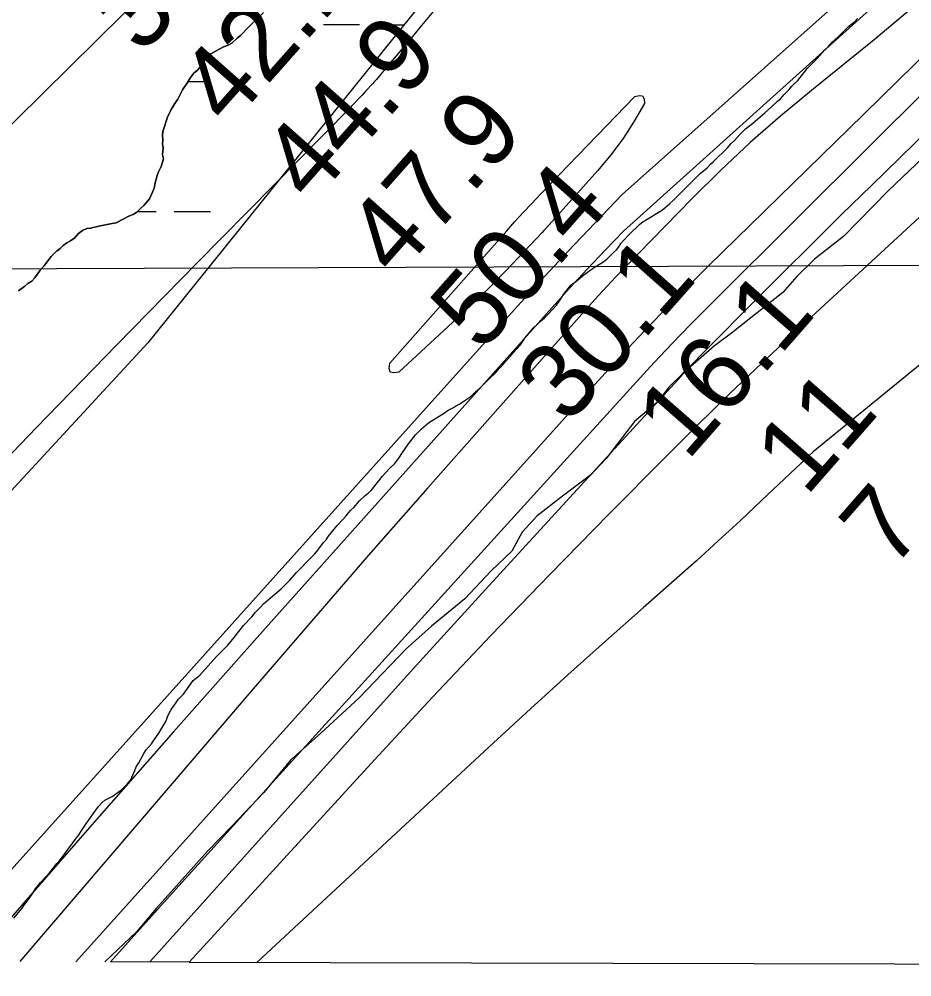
# Model space of a CAD drawing. Extents: x 3172297 to 3210190, y 958463 to 983887.
# Drawn here: x 3192652 to 3193444, y 963866 to 964716 of the extents above; entities that cross this region are included whole.
import ezdxf

# ---------------------------------------------------------------- set-up
doc = ezdxf.new("R2010")
doc.units = 0
for name, color, linetype in [('V-RIVR-EDGE', 7, 'Continuous'), ('V-RIVR-RANG', 7, 'Continuous'), ('V-SITE-VEGE', 7, 'Continuous'), ('V-TOPO-BNDY', 7, 'Continuous'), ('V-TOPO-DPTH', 7, 'Continuous'), ('V-TOPO-MAJR', 7, 'Continuous'), ('V-TOPO-MINR', 7, 'Continuous'), ('V-TOPO-SHOR', 7, 'Continuous'), ('V-TOPO-WATR', 7, 'Continuous'), ('V-WETL-SWMP', 7, 'Continuous')]:
    doc.layers.add(name, color=color, linetype=linetype)

msp = doc.modelspace()

# ---------------------------------------------------------------- linework, layer by layer
at = {"layer": 'V-RIVR-EDGE'}
msp.add_lwpolyline([(3193460.57, 964599.24), (3193422.95, 964563.51), (3193383.62, 964523.24), (3193357.7, 964502.84), (3193342.02, 964487.52), (3193329.48, 964473.34), (3193283.9, 964437.34), (3193268.81, 964426.01), (3193240.88, 964401.34), (3193228.34, 964389.15), (3193218.36, 964376.1), (3193197.85, 964358.81), (3193172.75, 964325.89), (3193159.07, 964311.14), (3193134, 964292.72), (3193111.5, 964274.87), (3193098.38, 964260.68), (3193089.25, 964243.79), (3193071.29, 964226.78), (3193047.63, 964201.53), (3193018, 964177.15), (3192995.5, 964157.02), (3192953.88, 964113.63), (3192919.69, 964082.44), (3192892.9, 964058.34), (3192869.23, 964029.69), (3192841.02, 963999.9), (3192819.64, 963978.07), (3192774.02, 963927), (3192756.35, 963906.01), (3192728.14, 963879.45)], dxfattribs=at)
at = {"layer": 'V-SITE-VEGE'}
for p, q in [((3192868.96, 964721.74), (3192861.75, 964714.48)), ((3192859.01, 964712.06), (3192856.26, 964709.3)), ((3192861.75, 964714.48), (3192859.01, 964712.06)), ((3193387.66, 964709.31), (3193393.26, 964713.64)), ((3193393.26, 964713.64), (3193395.84, 964716.24)), ((3192856.26, 964709.3), (3192848.71, 964701.35)), ((3193378.64, 964700.01), (3193387.66, 964709.31)), ((3192840.81, 964694.44), (3192837.71, 964692.7)), ((3192845.96, 964699.28), (3192840.81, 964694.44)), ((3192848.71, 964701.35), (3192845.96, 964699.28)), ((3193369.6, 964691.13), (3193373.26, 964695.24)), ((3193373.26, 964695.24), (3193378.64, 964700.01)), ((3192822.24, 964685.08), (3192819.15, 964682.31)), ((3192830.15, 964689.58), (3192822.24, 964685.08)), ((3192833.59, 964691.31), (3192830.15, 964689.58)), ((3192837.71, 964692.7), (3192833.59, 964691.31)), ((3193360.15, 964681.18), (3193366.16, 964687.89)), ((3193366.16, 964687.89), (3193369.6, 964691.13)), ((3192816.06, 964678.51), (3192812.64, 964672.99)), ((3192819.15, 964682.31), (3192816.06, 964678.51)), ((3193351.55, 964672.31), (3193360.15, 964681.18)), ((3192807.14, 964667.81), (3192804.4, 964664.01)), ((3192810.58, 964670.57), (3192807.14, 964667.81)), ((3192812.64, 964672.99), (3192810.58, 964670.57)), ((3193342.74, 964661.28), (3193351.55, 964672.31)), ((3192801.66, 964659.52), (3192797.2, 964652.96)), ((3192804.4, 964664.01), (3192801.66, 964659.52)), ((3193337.58, 964656.3), (3193342.74, 964661.28)), ((3192797.2, 964652.96), (3192793.09, 964644.68)), ((3193330.49, 964648.52), (3193335.21, 964653.49)), ((3193335.21, 964653.49), (3193337.58, 964656.3)), ((3192793.09, 964644.68), (3192790.35, 964640.88)), ((3193319.52, 964637.91), (3193324.9, 964643.1)), ((3193324.9, 964643.1), (3193327.48, 964645.05)), ((3193327.48, 964645.05), (3193330.49, 964648.52)), ((3192787.61, 964636.4), (3192784.19, 964629.84)), ((3192790.35, 964640.88), (3192787.61, 964636.4)), ((3193313.71, 964632.71), (3193319.52, 964637.91)), ((3192784.19, 964629.84), (3192779.75, 964616.05)), ((3193302.96, 964623.4), (3193307.26, 964627.3)), ((3193307.26, 964627.3), (3193313.71, 964632.71)), ((3193291.35, 964613.45), (3193296.29, 964618.42)), ((3193296.29, 964618.42), (3193302.96, 964623.4)), ((3192779.75, 964616.05), (3192779.42, 964612.95)), ((3192779.42, 964612.95), (3192779.78, 964608.82)), ((3192779.78, 964608.82), (3192779.45, 964605.03)), ((3193283.6, 964605.44), (3193286.62, 964608.25)), ((3193286.62, 964608.25), (3193291.35, 964613.45)), ((3192779.45, 964605.03), (3192780.15, 964601.58)), ((3192780.15, 964601.58), (3192779.48, 964595.38)), ((3193267.7, 964589.21), (3193280.38, 964601.76)), ((3193280.38, 964601.76), (3193283.6, 964605.44)), ((3192780.18, 964591.94), (3192778.13, 964585.05)), ((3192779.48, 964595.38), (3192780.18, 964591.94)), ((3192778.13, 964585.05), (3192775.74, 964580.21)), ((3193256.3, 964578.82), (3193262.54, 964584.02)), ((3193262.54, 964584.02), (3193265.33, 964587.05)), ((3193265.33, 964587.05), (3193267.7, 964589.21)), ((3192774.71, 964577.11), (3192773.01, 964570.56)), ((3192775.74, 964580.21), (3192774.71, 964577.11)), ((3193232.65, 964555.23), (3193253.72, 964576.44)), ((3193253.72, 964576.44), (3193256.3, 964578.82)), ((3192773.01, 964570.56), (3192772, 964565.74)), ((3192770.63, 964562.29), (3192767.89, 964556.42)), ((3192772, 964565.74), (3192770.63, 964562.29)), ((3192762.74, 964550.55), (3192760, 964547.79)), ((3192767.89, 964556.42), (3192762.74, 964550.55)), ((3193222.76, 964546.57), (3193229.43, 964552.2)), ((3193229.43, 964552.2), (3193232.65, 964555.23)), ((3192750.03, 964541.21), (3192738.34, 964534.97)), ((3192753.47, 964542.6), (3192750.03, 964541.21)), ((3192756.56, 964544.68), (3192753.47, 964542.6)), ((3192760, 964547.79), (3192756.56, 964544.68)), ((3193205.32, 964535.95), (3193222.76, 964546.57)), ((3192722.85, 964532.17), (3192715.62, 964530.42)), ((3192734.9, 964534.61), (3192722.85, 964532.17)), ((3192738.34, 964534.97), (3192734.9, 964534.61)), ((3193193.28, 964524.69), (3193202.74, 964533.78)), ((3193202.74, 964533.78), (3193205.32, 964535.95)), ((3192704.96, 964525.56), (3192701.19, 964521.07)), ((3192708.4, 964528.33), (3192704.96, 964525.56)), ((3192712.18, 964530.07), (3192708.4, 964528.33)), ((3192715.62, 964530.42), (3192712.18, 964530.07)), ((3193188.55, 964519.72), (3193193.28, 964524.69)), ((3192691.21, 964514.84), (3192688.81, 964512.42)), ((3192694.65, 964517.26), (3192691.21, 964514.84)), ((3192697.75, 964518.99), (3192694.65, 964517.26)), ((3192700.84, 964521.07), (3192697.75, 964518.99)), ((3192701.19, 964521.07), (3192700.84, 964521.07)), ((3193184.04, 964513.66), (3193185.97, 964516.69)), ((3193185.97, 964516.69), (3193188.55, 964519.72)), ((3192685.38, 964510), (3192680.57, 964505.16)), ((3192686.06, 964510.35), (3192685.38, 964510)), ((3192688.81, 964512.42), (3192686.06, 964510.35)), ((3193173.5, 964502.84), (3193179.31, 964508.9)), ((3193179.31, 964508.9), (3193181.89, 964511.07)), ((3193181.89, 964511.07), (3193184.04, 964513.66)), ((3192676.8, 964500.33), (3192674.4, 964496.88)), ((3192680.57, 964505.16), (3192676.8, 964500.33)), ((3193160.81, 964494.61), (3193170.92, 964500.89)), ((3193170.92, 964500.89), (3193173.5, 964502.84)), ((3192670.96, 964493.08), (3192666.16, 964486.17)), ((3192674.4, 964496.88), (3192670.96, 964493.08)), ((3193151.98, 964488.11), (3193160.81, 964494.61)), ((3192659.98, 964481.33), (3192657.23, 964478.91)), ((3192663.42, 964483.41), (3192659.98, 964481.33)), ((3192666.16, 964486.17), (3192663.42, 964483.41)), ((3193141.66, 964479.88), (3193147.04, 964483.99)), ((3193147.04, 964483.99), (3193151.98, 964488.11)), ((3192657.23, 964478.91), (3192651.74, 964474.76)), ((3193135, 964471.44), (3193139.08, 964476.85)), ((3193139.08, 964476.85), (3193141.66, 964479.88)), ((3193128.77, 964461.93), (3193130.71, 964464.31)), ((3193130.71, 964464.31), (3193135, 964471.44)), ((3193121.46, 964453.93), (3193128.77, 964461.93)), ((3193108.56, 964442.02), (3193115.87, 964448.73)), ((3193115.87, 964448.73), (3193118.24, 964450.68)), ((3193118.24, 964450.68), (3193121.46, 964453.93)), ((3193100.83, 964432.72), (3193108.56, 964442.02)), ((3193096.96, 964426.89), (3193100.83, 964432.72)), ((3193090.52, 964419.75), (3193096.96, 964426.89)), ((3193083.43, 964411.75), (3193088.15, 964416.72)), ((3193088.15, 964416.72), (3193090.52, 964419.75)), ((3193075.04, 964402.23), (3193078.27, 964406.12)), ((3193078.27, 964406.12), (3193080.85, 964408.72)), ((3193080.85, 964408.72), (3193083.43, 964411.75)), ((3193060.42, 964388.16), (3193070.1, 964397.68)), ((3193070.1, 964397.68), (3193072.68, 964399.85)), ((3193072.68, 964399.85), (3193075.04, 964402.23)), ((3193057.63, 964385.78), (3193060.42, 964388.16)), ((3193045.8, 964376.25), (3193050.96, 964379.93)), ((3193050.96, 964379.93), (3193053.97, 964382.32)), ((3193053.97, 964382.32), (3193057.63, 964385.78)), ((3193032.88, 964368.87), (3193037.4, 964371.26)), ((3193037.4, 964371.26), (3193039.12, 964372.56)), ((3193039.12, 964372.56), (3193043, 964374.51)), ((3193043, 964374.51), (3193045.8, 964376.25)), ((3193015.44, 964357.6), (3193029.43, 964366.49)), ((3193029.43, 964366.49), (3193032.88, 964368.87)), ((3193009.2, 964352.41), (3193015.44, 964357.6)), ((3192997.6, 964338.99), (3193003.83, 964346.99)), ((3193003.83, 964346.99), (3193009.2, 964352.41)), ((3192991.59, 964330.56), (3192997.6, 964338.99)), ((3192989.66, 964327.32), (3192991.59, 964330.56)), ((3192980.85, 964317.16), (3192985.36, 964321.7)), ((3192985.36, 964321.7), (3192989.66, 964327.32)), ((3192974.62, 964310.45), (3192980.85, 964317.16)), ((3192964.52, 964297.69), (3192974.62, 964310.45)), ((3192959.14, 964293.14), (3192961.94, 964295.31)), ((3192961.94, 964295.31), (3192964.52, 964297.69)), ((3192949.04, 964282.54), (3192954.2, 964288.38)), ((3192954.2, 964288.38), (3192959.14, 964293.14)), ((3192942.38, 964275.19), (3192944.31, 964277.78)), ((3192944.31, 964277.78), (3192946.46, 964280.16)), ((3192946.46, 964280.16), (3192949.04, 964282.54)), ((3192934.42, 964266.53), (3192939.8, 964272.59)), ((3192939.8, 964272.59), (3192942.38, 964275.19)), ((3192926.69, 964257.23), (3192934.42, 964266.53)), ((3192916.38, 964243.61), (3192922.18, 964251.39)), ((3192922.18, 964251.39), (3192924.54, 964253.99)), ((3192924.54, 964253.99), (3192926.69, 964257.23)), ((3192914.23, 964241.01), (3192916.38, 964243.61)), ((3192906.71, 964233.87), (3192914.23, 964241.01)), ((3192898.11, 964224.78), (3192902.62, 964229.33)), ((3192902.62, 964229.33), (3192906.71, 964233.87)), ((3192888.01, 964213.54), (3192892.73, 964218.51)), ((3192892.73, 964218.51), (3192898.11, 964224.78)), ((3192875.32, 964202.28), (3192884.78, 964210.5)), ((3192884.78, 964210.5), (3192888.01, 964213.54)), ((3192869.08, 964197.08), (3192875.32, 964202.28)), ((3192861.55, 964189.29), (3192866.71, 964194.49)), ((3192866.71, 964194.49), (3192869.08, 964197.08)), ((3192851.24, 964177.82), (3192858.54, 964185.62)), ((3192858.54, 964185.62), (3192861.55, 964189.29)), ((3192842.86, 964167.23), (3192851.24, 964177.82)), ((3192837.27, 964160.53), (3192842.86, 964167.23)), ((3192827.39, 964150.35), (3192837.27, 964160.53)), ((3192819.86, 964142.13), (3192827.39, 964150.35)), ((3192814.92, 964136.3), (3192819.86, 964142.13)), ((3192806.75, 964128.94), (3192812.56, 964133.91)), ((3192812.56, 964133.91), (3192814.92, 964136.3)), ((3192798.16, 964117.04), (3192806.75, 964128.94)), ((3192793.43, 964112.07), (3192798.16, 964117.04)), ((3192788.49, 964105.36), (3192791.07, 964108.61)), ((3192791.07, 964108.61), (3192793.43, 964112.07)), ((3192783.56, 964095.86), (3192784.85, 964098.88)), ((3192784.85, 964098.88), (3192786.77, 964102.77)), ((3192786.77, 964102.77), (3192788.49, 964105.36)), ((3192776.27, 964082.25), (3192782.5, 964092.62)), ((3192782.5, 964092.62), (3192783.56, 964095.86)), ((3192771.33, 964075.54), (3192776.27, 964082.25)), ((3192764.89, 964067.54), (3192769.62, 964072.95)), ((3192769.62, 964072.95), (3192771.33, 964075.54)), ((3192762.74, 964064.3), (3192764.89, 964067.54)), ((3192758.46, 964055.88), (3192760.38, 964059.98)), ((3192760.38, 964059.98), (3192762.74, 964064.3)), ((3192750.96, 964040.75), (3192754.81, 964049.18)), ((3192754.81, 964049.18), (3192756.09, 964052.42)), ((3192756.09, 964052.42), (3192758.46, 964055.88)), ((3192749.02, 964038.16), (3192750.96, 964040.75)), ((3192740.21, 964029.93), (3192743, 964032.1)), ((3192743, 964032.1), (3192746.66, 964035.56)), ((3192746.66, 964035.56), (3192749.02, 964038.16)), ((3192725.57, 964020.39), (3192728.36, 964022.99)), ((3192728.36, 964022.99), (3192734.83, 964026.25)), ((3192734.83, 964026.25), (3192740.21, 964029.93)), ((3192717.83, 964010.88), (3192722.56, 964017.15)), ((3192722.56, 964017.15), (3192725.57, 964020.39)), ((3192711.39, 964001.58), (3192717.83, 964010.88)), ((3192707.96, 963996.18), (3192711.39, 964001.58)), ((3192688.21, 963969.15), (3192705.81, 963993.15)), ((3192705.81, 963993.15), (3192707.96, 963996.18)), ((3192679.18, 963958.34), (3192685.84, 963966.56)), ((3192685.84, 963966.56), (3192688.21, 963969.15)), ((3192671.23, 963949.69), (3192675.74, 963954.45)), ((3192675.74, 963954.45), (3192679.18, 963958.34)), ((3192667.15, 963944.71), (3192669.3, 963947.09)), ((3192669.3, 963947.09), (3192671.23, 963949.69)), ((3192659.21, 963932.82), (3192664.57, 963940.39)), ((3192664.57, 963940.39), (3192667.15, 963944.71)), ((3192654.7, 963926.77), (3192657.06, 963930.23)), ((3192657.06, 963930.23), (3192659.21, 963932.82)), ((3192647.6, 963918.12), (3192654.7, 963926.77))]:
    msp.add_line(p, q, dxfattribs=at)
at = {"layer": 'V-TOPO-BNDY'}
msp.add_lwpolyline([(3186048.77, 963895.97), (3186249.57, 964469.98), (3198733.3, 964517.56), (3198114.71, 963866.13)], dxfattribs=at)
at = {"layer": 'V-TOPO-DPTH'}
for points in [[(3192733.41, 963879.44), (3192788.38, 963940.57), (3192853.74, 964012.88), (3193199.65, 964394.08), (3193215.4, 964411.17), (3193231.33, 964428.1), (3193247.51, 964444.77), (3193263.87, 964461.28), (3193345.62, 964542.53), (3193402.96, 964599.56), (3193460.25, 964656.64), (3193517.49, 964713.78), (3193574.68, 964770.96), (3193820.31, 965016.76), (3193844.13, 965040.65), (3193867.91, 965064.58), (3193891.64, 965088.56), (3193915.33, 965112.59), (3193941.75, 965139.43), (3193952.38, 965149.86)], [(3193523, 964607.44), (3193442.73, 964532.71), (3193339.59, 964437.45), (3193310.77, 964410.48), (3193282.19, 964383.25), (3193253.98, 964355.66), (3193226.01, 964327.81), (3193175.55, 964276.92), (3193122.85, 964223.13), (3193070.58, 964168.94), (3193018.94, 964114.14), (3192967.73, 964058.93), (3192803.03, 963879.27), (3192733.41, 963879.44)], [(3193523, 964607.44), (3193442.73, 964532.71), (3193339.59, 964437.45), (3193310.77, 964410.48), (3193282.19, 964383.25), (3193253.98, 964355.66), (3193226.01, 964327.81), (3193175.55, 964276.92), (3193122.85, 964223.13), (3193070.58, 964168.94), (3193018.94, 964114.14), (3192967.73, 964058.93), (3192803.03, 963879.27)], [(3192803.03, 963879.27), (3193929.39, 963876.48), (3193946.55, 963889.58), (3194000.05, 963932.78), (3194051.98, 963977.9), (3194102.93, 964024.06), (3194152.42, 964071.79), (3194200.93, 964120.56)]]:
    msp.add_lwpolyline(points, dxfattribs=at)
at = {"layer": 'V-TOPO-MAJR'}
for points in [[(3194548.52, 965780.85), (3193836.47, 965119.63), (3193829.55, 965112.21), (3193822.6, 965104.81), (3193815.61, 965097.46), (3193808.59, 965090.13), (3193756.42, 965035.99), (3193731.54, 965011.09), (3193706.09, 964986.81), (3193679.77, 964963.47), (3193652.89, 964940.74), (3193625.45, 964918.66), (3193597.83, 964896.79), (3193188.29, 964527.84), (3193172.18, 964511.1), (3193156.23, 964494.23), (3193140.49, 964477.14), (3193124.91, 964459.92), (3192868.12, 964172.41), (3192789.09, 964083.38), (3192710.43, 963994.03), (3192632.33, 963904.2), (3192611.24, 963879.74)], [(3192625.74, 964603.05), (3192815.55, 964790.54)]]:
    msp.add_lwpolyline(points, dxfattribs=at)
at = {"layer": 'V-TOPO-MINR'}
for points in [[(3194372.18, 966226.17), (3193580.04, 965390.46), (3193562.15, 965371.22), (3193544.51, 965351.76), (3193527.25, 965331.96), (3193510.25, 965311.93), (3193009.1, 964710.23), (3193002.17, 964701.92), (3192995.24, 964693.61), (3192988.3, 964685.31), (3192981.36, 964677.01), (3192969.12, 964662.37), (3192968.29, 964661.4), (3192967.46, 964660.43), (3192965.75, 964658.52), (3192960.13, 964652.39), (3192956.44, 964648.39), (3192952.71, 964644.43), (3192948.94, 964640.51), (3192945.15, 964636.61), (3192809.87, 964499.28), (3192738.63, 964426.54), (3192667.68, 964353.51), (3192597.16, 964280.07)], [(3194767.1, 965937.76), (3193830.3, 965059.43), (3193810.02, 965038.88), (3193701.62, 964929.53), (3193626.91, 964854.54), (3193551.97, 964779.78), (3193476.67, 964705.39), (3193401.13, 964631.23), (3193263.23, 964496.51), (3193237.51, 964470.9), (3193212.14, 964444.95), (3193187.28, 964418.52), (3193162.76, 964391.76), (3192702.43, 963879.51)], [(3192571.81, 963879.84), (3193091.53, 964458.07), (3193115.05, 964483.92), (3193138.78, 964509.58), (3193162.82, 964534.94), (3193187.06, 964560.11), (3193751.04, 965062.55), (3193756.82, 965066.65), (3193762.54, 965070.82), (3193768.19, 965075.08), (3193773.79, 965079.41), (3193779.25, 965083.91), (3193784.57, 965088.55), (3193789.7, 965093.41), (3193794.69, 965098.42), (3193807.75, 965112.12), (3193809.26, 965113.72), (3193810.75, 965115.34), (3193813.66, 965118.64), (3194212.02, 965582.11)], [(3194337.29, 965186.04), (3194060.17, 964919.58), (3194053.22, 964912.89), (3194046.26, 964906.2), (3194039.3, 964899.51), (3194032.34, 964892.82), (3193974.24, 964836.98), (3193966.61, 964830.25), (3193356.48, 964332), (3193352.64, 964328.36), (3193348.8, 964324.72), (3193344.95, 964321.07), (3193341.11, 964317.43), (3193310.72, 964288.63), (3193291.58, 964270.69), (3193272.31, 964252.89), (3193252.85, 964235.31), (3193233.26, 964217.88), (3193205.58, 964193.52), (3193172.17, 964163.89), (3193138.91, 964134.07), (3193105.9, 964103.99), (3193073.04, 964073.74), (3192863.38, 963879.12)], [(3193952.38, 965149.86), (3193941.75, 965139.43), (3193915.33, 965112.59), (3193891.64, 965088.56), (3193867.91, 965064.58), (3193844.13, 965040.65), (3193820.31, 965016.76), (3193574.68, 964770.96), (3193517.49, 964713.78), (3193460.25, 964656.64), (3193402.96, 964599.56), (3193345.62, 964542.53), (3193263.87, 964461.28), (3193247.51, 964444.77), (3193231.33, 964428.1), (3193215.4, 964411.17), (3193199.65, 964394.08), (3192853.74, 964012.88), (3192788.38, 963940.57), (3192733.41, 963879.44)], [(3193465.34, 964743.33), (3193437.93, 964720.39), (3193410.39, 964697.59), (3193382.69, 964675), (3193354.86, 964652.56), (3193327.39, 964629.74), (3193300.52, 964606.26), (3193274.53, 964581.81), (3193249.13, 964556.7), (3193189.52, 964495.56), (3193181.55, 964487.27), (3193173.65, 964478.9), (3193165.87, 964470.42), (3193158.17, 964461.87), (3193067.56, 964359.85), (3193014.79, 964300.09), (3192962.24, 964240.13), (3192910.02, 964179.88), (3192858.02, 964119.44), (3192652.89, 963879.64)], [(3193547.33, 964704.17), (3193408.13, 964568.3), (3193381.65, 964542.34), (3193355.25, 964516.29), (3193328.97, 964490.12), (3193302.77, 964463.87), (3193264.86, 964425.71), (3193257.72, 964418.44), (3193250.64, 964411.11), (3193243.65, 964403.71), (3193236.72, 964396.24), (3193127.29, 964276.99), (3193065.81, 964209.75), (3193004.5, 964142.35), (3192943.43, 964074.74), (3192882.53, 964006.97), (3192768.25, 963879.35)], [(3193187.98, 964609.98), (3193177.1, 964595.49), (3193165.48, 964581.52), (3193119.34, 964530.16), (3193117.6, 964528.25), (3193115.85, 964526.35), (3193095.24, 964504.26), (3193083.93, 964492.39), (3193072.46, 964480.7), (3193060.73, 964469.25), (3193048.83, 964457.98), (3192989.14, 964402.64), (3192984.45, 964401.91), (3192981.28, 964402.74), (3192980.38, 964405.89), (3192980.99, 964410.59), (3193084.69, 964528), (3193092, 964536.18), (3193099.38, 964544.28), (3193106.87, 964552.29), (3193114.43, 964560.23), (3193198.24, 964647.15), (3193202.21, 964648.19), (3193205.12, 964647.77), (3193206.45, 964645.14), (3193206.72, 964641.05), (3193197.72, 964625.26), (3193187.98, 964609.98)]]:
    msp.add_lwpolyline(points, dxfattribs=at)
at = {"layer": 'V-TOPO-SHOR'}
for points in [[(3192861.76, 964714.48), (3192868.96, 964721.74)], [(3192651.74, 964474.76), (3192657.23, 964478.91), (3192659.98, 964481.33), (3192663.42, 964483.41), (3192666.16, 964486.17), (3192670.96, 964493.08), (3192674.4, 964496.88), (3192676.8, 964500.33), (3192680.57, 964505.16), (3192685.38, 964510), (3192686.06, 964510.35), (3192688.81, 964512.42), (3192691.21, 964514.84), (3192694.65, 964517.26), (3192697.75, 964518.99), (3192700.84, 964521.07), (3192701.19, 964521.07), (3192704.96, 964525.56), (3192708.4, 964528.33), (3192712.18, 964530.07), (3192715.62, 964530.42), (3192722.85, 964532.17), (3192734.9, 964534.61), (3192738.34, 964534.97), (3192750.03, 964541.21), (3192753.47, 964542.6), (3192756.56, 964544.68), (3192760, 964547.79), (3192762.74, 964550.55), (3192767.89, 964556.42), (3192770.63, 964562.29), (3192772, 964565.74), (3192773.01, 964570.56), (3192774.71, 964577.11), (3192775.74, 964580.21), (3192778.13, 964585.05), (3192780.18, 964591.94), (3192779.48, 964595.38), (3192780.15, 964601.58), (3192779.45, 964605.03), (3192779.78, 964608.82), (3192779.42, 964612.95), (3192779.75, 964616.05), (3192784.19, 964629.84), (3192787.61, 964636.4), (3192790.35, 964640.88), (3192793.09, 964644.68), (3192797.2, 964652.96), (3192801.66, 964659.52), (3192804.4, 964664.01), (3192807.14, 964667.81), (3192810.58, 964670.57), (3192812.64, 964672.99), (3192816.06, 964678.51), (3192819.15, 964682.31), (3192822.24, 964685.08), (3192830.15, 964689.58), (3192833.59, 964691.31), (3192837.71, 964692.7), (3192840.81, 964694.44), (3192845.96, 964699.28), (3192848.71, 964701.35), (3192856.26, 964709.3), (3192859.01, 964712.06), (3192861.76, 964714.48)]]:
    msp.add_lwpolyline(points, dxfattribs=at)
at = {"layer": 'V-TOPO-WATR'}
msp.add_lwpolyline([(3193523, 964607.44), (3193442.73, 964532.71), (3193339.59, 964437.45), (3193310.77, 964410.48), (3193282.19, 964383.25), (3193253.98, 964355.66), (3193226.01, 964327.81), (3193175.55, 964276.92), (3193122.85, 964223.13), (3193070.58, 964168.94), (3193018.94, 964114.14), (3192967.73, 964058.93), (3192803.03, 963879.27)], dxfattribs=at)
at = {"layer": 'V-WETL-SWMP'}
for p, q in [((3192922.26, 964710.99), (3192954.26, 964710.91)), ((3192970.26, 964710.87), (3192993.66, 964710.81)), ((3192802.28, 964660.55), (3192817.54, 964660.51)), ((3192757.17, 964545.23), (3192773.85, 964545.18)), ((3192789.85, 964545.14), (3192821.85, 964545.07))]:
    msp.add_line(p, q, dxfattribs=at)
for points in [[(3193738.09, 965817.65), (3193624.49, 965630.72), (3193522.75, 965444.79), (3193444.26, 965323.8), (3193348.56, 965185.35), (3193249.16, 965054.18), (3193135.29, 964906.47), (3193014.29, 964734.08), (3193007.95, 964728.57), (3192766.54, 964428.5), (3192623.52, 964274.2)], [(3192861.76, 964714.48), (3192868.96, 964721.74)], [(3192651.74, 964474.76), (3192657.23, 964478.91), (3192659.98, 964481.33), (3192663.42, 964483.41), (3192666.17, 964486.17), (3192670.96, 964493.08), (3192674.4, 964496.88), (3192676.8, 964500.33), (3192680.57, 964505.16), (3192685.38, 964510), (3192686.06, 964510.35), (3192688.81, 964512.42), (3192691.22, 964514.84), (3192694.65, 964517.26), (3192697.75, 964518.99), (3192700.84, 964521.07), (3192701.19, 964521.07), (3192704.96, 964525.56), (3192708.4, 964528.33), (3192712.18, 964530.06), (3192715.62, 964530.42), (3192722.85, 964532.17), (3192734.9, 964534.62), (3192738.34, 964534.97), (3192750.03, 964541.21), (3192753.47, 964542.6), (3192756.56, 964544.68), (3192760, 964547.79), (3192762.74, 964550.55), (3192767.89, 964556.42), (3192770.63, 964562.29), (3192772, 964565.74), (3192773.01, 964570.56), (3192774.71, 964577.11), (3192775.74, 964580.21), (3192778.13, 964585.05), (3192780.18, 964591.94), (3192779.48, 964595.38), (3192780.15, 964601.58), (3192779.45, 964605.03), (3192779.78, 964608.82), (3192779.42, 964612.95), (3192779.75, 964616.05), (3192784.19, 964629.84), (3192787.61, 964636.4), (3192790.35, 964640.89), (3192793.09, 964644.68), (3192797.2, 964652.96), (3192801.66, 964659.52), (3192804.4, 964664.01), (3192807.14, 964667.81), (3192810.58, 964670.57), (3192812.64, 964672.99), (3192816.06, 964678.51), (3192819.15, 964682.31), (3192822.24, 964685.08), (3192830.15, 964689.58), (3192833.59, 964691.31), (3192837.71, 964692.7), (3192840.81, 964694.44), (3192845.96, 964699.28), (3192848.71, 964701.35), (3192856.26, 964709.3), (3192859.01, 964712.06), (3192861.76, 964714.48)]]:
    msp.add_lwpolyline(points, dxfattribs=at)

# ---------------------------------------------------------------- texts
at = {"layer": 'V-RIVR-RANG'}
for s, rotation, p in [('39.9', 48.49833, (3192761.7, 964682.96)), ('42.1', 48.49833, (3192838.51, 964618.86)), ('44.9', 48.49833, (3192911.82, 964550.81)), ('47.9', 48.49833, (3192986.87, 964484.73)), ('50.4', 48.49833, (3193062.11, 964418.85)), ('30.1', 48.49833, (3193138.74, 964354.55)), ('16.1', 48.78694, (3193244.76, 964322.94)), ('11', 48.78694, (3193350.06, 964291.39)), ('7', 48.78694, (3193425.99, 964226.3))]:
    msp.add_text(s, height=67, rotation=rotation, dxfattribs=at).set_placement(p)

doc.saveas('drawing.dxf')
